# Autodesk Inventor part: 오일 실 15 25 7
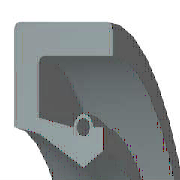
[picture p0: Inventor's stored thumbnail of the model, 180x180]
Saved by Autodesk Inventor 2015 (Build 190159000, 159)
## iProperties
Created: 2012-02
Part Number: 오일 실 15 25 7
Material: 고무
Description: 오일-실
Document SubType Name: Modeling
Standard: KS B 2804
Designer: mduedu
Standards Organization: KS
Language: ko-KR
Size Designation: S - 15 25 7
Categories: <MemberInstance><Categories><Category DisplayName="샤프트 부품" InternalName="7f7aeb1f-a693-4053-b835-cee3144e0d98" Mnemonic="SHFT"><Category DisplayName="실링" Intern
Density: 0.93 g/cm^3
Appearance: 고무 - 검은색 - 버전 1.1
IsCustomPart: 1
Author: mduedu
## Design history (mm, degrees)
revolve "본체" stored, may be unused: angle "d17" = 90 deg
revolve "스프링1" stored, may be unused: angle "d18" = 90 deg
body "Solid1"
sketch "스케치1"
  geometry: L1 (0, 12.5)-(7, 12.5); L2 (7, 12.5)-(7, 11.25); L3 (7, 11.25)-(1.75, 11.25); L4 (0, 12.5)-(0, 9.6); L5 (0, 9.6)-(1.75, 9.25); L6 (1.75, 9.25)-(4.9, 7.5); L7 (4.9, 7.5)-(0, 7.5); L8 (6.3, 8.375)-(6.3, 9.6); L9 (0, 0)-(9.586, 0) reference; L10 (4.9, 7.5)-(6.3, 8.375); L11 (0, 18)-(0, -3) reference; L12 (-1.917, 0)-(11.503, 0) reference; L13 (4.2, 9.6)-(1.75, 10.09); L14 (1.75, 10.09)-(1.75, 11.25); L15 (6.3, 9.6)-(5.6, 9.6); C1 r 0.455 at (4.9, 9.6); A1 r 0.7 centre (4.9, 9.6) between (5.6, 9.6) and (4.2, 9.6)
  constraints: 26 end point, 5 horizontal alignment, 4 perpendicular, 2 centre point, 2 collinear, 2 horizontal, 2 parallel, 2 point on circle, 2 point on line, 2 vertical alignment, 1 coincident
  dimensions: "d0" = 25 diameter of L1 L9 (= SD2); "d1" = 16.75 diameter of L8.start L9 (= ABDM); "d2" = 1.25 distance of L1.end L2.end (computed from SD); "d3" = 0.91 diameter of C1 (= SPDI); "d4" = 1.4 diameter of A1 (= SPDA); "d5" = 15 diameter of L6.end L9 (= NND); "d6" = 18.5 diameter of L5.end L9 (= TKDM); "d7" = 19.2 diameter of L4.end L9 (= HLDM); "d8" = 4.9 distance from line of C1.centre L4 (= SPDST); "d9" = 6.3 distance between parallel lines of L8 L4 (= SDI); "d10" = 7 distance between parallel lines of L2 L4 (= SWDT); "d12" = 1.75 distance between parallel lines of L14 L4 (= SD)
fillet "모깎기1" dims "d11" = 0.3 (= RR)
other parameters: "SD2" = 25 [user parameter; used in 1 equation term], "SWDT" = 7 [user parameter; used in 1 equation term], "RR" = 0.3 [user parameter; used in 1 equation term], "SD" = 1.75 [user parameter; used in 2 equation terms], "NND" = 15 [user parameter; used in 1 equation term], "SPDA" = 1.4 [user parameter; used in 1 equation term], "SPDI" = 0.91 [user parameter; used in 1 equation term], "TKDM" = 18.5 [user parameter; used in 1 equation term], "HLDM" = 19.2 [user parameter; used in 1 equation term], "ABDM" = 16.75 [user parameter; used in 1 equation term], "SDI" = 6.3 [user parameter; used in 1 equation term], "SPDST" = 4.9 [user parameter; used in 1 equation term], "d13" = 0, "d14" = 0, "d15" = 0, "LAB" = 0.35 [user parameter]
